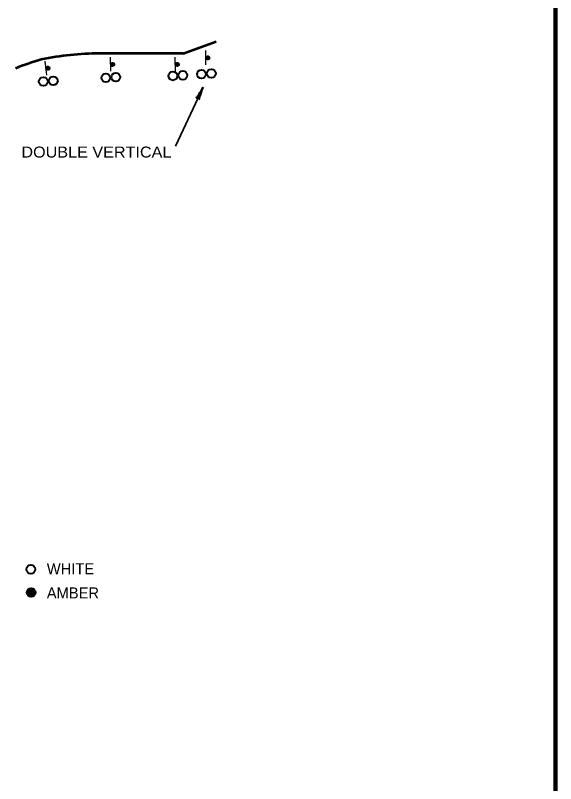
# Model space of a CAD drawing. Extents: x 393 to 1249, y -102 to 530.
# Drawn here: x 1122.7 to 1242.2, y 155.6 to 325.7 of the extents above; entities that cross this region are included whole.
import ezdxf
from ezdxf.enums import TextEntityAlignment as Align

# ---------------------------------------------------------------- set-up
doc = ezdxf.new("R2010")
doc.units = 0
doc.header["$LTSCALE"] = 0.97
doc.layers.add('1', color=7, linetype='Continuous', lineweight=40)
doc.layers.add('4', color=7, linetype='Continuous', lineweight=25)

msp = doc.modelspace()

# ---------------------------------------------------------------- linework, layer by layer
at = {"layer": '1', "lineweight": 158}
msp.add_line((1242.1684, -2.8845), (1242.1684, 523.2155), dxfattribs=at)
at = {"layer": '1', "lineweight": 13}
msp.add_line((1242.1684, -2.8845), (1242.1684, 523.2155), dxfattribs=at)
at = {"layer": '1', "lineweight": 53}
for q in [(1167.0635, 319.8655), (1141.2885, 317.206)]:
    msp.add_line((1159.7565, 317.206), q, dxfattribs=at)
at = {"layer": '1', "lineweight": 35}
msp.add_line((1158.0652, 296.7177), (1164.1645, 309.7296), dxfattribs=at)
at = {"layer": '1'}
for centre, radius in [((1165.1956, 316.2264), 0.3791), ((1165.1861, 316.2165), 0.35), ((1165.1958, 316.2167), 0.3305), ((1165.2147, 316.2462), 0.3402), ((1165.1956, 316.2264), 0.3013), ((1165.1956, 316.2264), 0.2819), ((1165.1958, 316.2167), 0.2722), ((1165.1958, 316.2167), 0.2527), ((1165.2055, 316.2169), 0.2335), ((1165.2152, 316.217), 0.2138), ((1165.2152, 316.217), 0.1944), ((1165.1961, 316.1972), 0.1555), ((1165.2347, 316.2174), 0.175), ((1165.196, 316.207), 0.1069), ((1165.2544, 316.1983), 0.1555), ((1165.264, 316.2082), 0.1461), ((1165.2739, 316.1986), 0.1166), ((1165.2836, 316.1988), 0.0977), ((1165.2933, 316.1989), 0.0778), ((1165.2321, 316.3631), 0.00972), ((1144.1669, 314.7907), 0.3791), ((1144.1573, 314.7808), 0.35), ((1144.1671, 314.781), 0.3305), ((1144.186, 314.8105), 0.3402), ((1144.1669, 314.7907), 0.3013), ((1144.1669, 314.7907), 0.2819), ((1144.1671, 314.781), 0.2722), ((1144.1671, 314.781), 0.2527), ((1144.1768, 314.7811), 0.2335), ((1144.1865, 314.7813), 0.2138), ((1144.1865, 314.7813), 0.1944), ((1144.1674, 314.7615), 0.1555), ((1144.2059, 314.7816), 0.175), ((1144.1672, 314.7712), 0.1069), ((1144.2257, 314.7625), 0.1555), ((1144.2353, 314.7724), 0.1461), ((1144.2451, 314.7629), 0.1166), ((1144.2549, 314.763), 0.0977), ((1144.2646, 314.7632), 0.0778), ((1144.2034, 314.9274), 0.00972), ((1144.284, 314.7636), 0.0583), ((1144.3035, 314.7639), 0.0389), ((1144.3229, 314.7642), 0.0194), ((1158.4394, 314.7907), 0.3791), ((1158.4299, 314.7808), 0.35), ((1158.4396, 314.781), 0.3305), ((1158.4585, 314.8105), 0.3402), ((1158.4394, 314.7907), 0.3013), ((1158.4394, 314.7907), 0.2819), ((1158.4396, 314.781), 0.2722), ((1158.4396, 314.781), 0.2527), ((1158.4493, 314.7811), 0.2335), ((1158.459, 314.7813), 0.2138), ((1158.459, 314.7813), 0.1944), ((1158.4399, 314.7615), 0.1555), ((1158.4785, 314.7816), 0.175), ((1158.4398, 314.7712), 0.1069), ((1158.4982, 314.7625), 0.1555), ((1158.5078, 314.7724), 0.1461), ((1158.5177, 314.7629), 0.1166), ((1158.5274, 314.763), 0.0977), ((1158.5371, 314.7632), 0.0778), ((1158.4759, 314.9274), 0.00972), ((1158.5565, 314.7636), 0.0583), ((1158.576, 314.7639), 0.0389), ((1158.5954, 314.7642), 0.0194), ((1165.3128, 316.1993), 0.0583), ((1165.3322, 316.1996), 0.0389), ((1165.3516, 316.2), 0.0194), ((1129.8321, 313.9483), 0.3791), ((1129.8236, 313.9375), 0.35), ((1129.8333, 313.9387), 0.3305), ((1129.849, 313.97), 0.3402), ((1129.8321, 313.9483), 0.3013), ((1129.8321, 313.9483), 0.2819), ((1129.8333, 313.9387), 0.2722), ((1129.8333, 313.9387), 0.2527), ((1129.8429, 313.9398), 0.2335), ((1129.8526, 313.941), 0.2138), ((1129.8526, 313.941), 0.1944), ((1129.8357, 313.9194), 0.1555), ((1129.8719, 313.9434), 0.175), ((1129.8345, 313.929), 0.1069), ((1129.8935, 313.9265), 0.1555), ((1129.902, 313.9373), 0.1461), ((1129.9128, 313.9288), 0.1166), ((1129.9225, 313.93), 0.0977), ((1129.8541, 314.0881), 0.00972), ((1129.9321, 313.9312), 0.0778), ((1129.9514, 313.9336), 0.0583), ((1129.9707, 313.9359), 0.0389), ((1129.99, 313.9383), 0.0194), ((1144.8664, 311.9768), 0.972), ((1157.5134, 312.2419), 0.972), ((1159.7079, 312.3834), 0.972), ((1163.816, 312.6485), 0.972), ((1166.0105, 312.7901), 0.972), ((1128.847, 311.022), 0.972), ((1131.0415, 311.1636), 0.972), ((1142.6719, 311.8352), 0.972), ((1126.0652, 203.0406), 0.972), ((1126.1406, 197.9056), 0.972), ((1126.1274, 197.9483), 0.8529), ((1125.7081, 197.6815), 0.3923), ((1126.1147, 197.923), 0.7878), ((1126.1275, 197.8848), 0.7017), ((1126.0512, 197.6307), 0.6228), ((1126.1147, 197.9611), 0.5846), ((1126.2672, 197.7705), 0.6414), ((1126.0893, 197.8848), 0.4322), ((1126.191, 197.8086), 0.5216), ((1126.1401, 198.139), 0.3831), ((1126.1147, 197.9484), 0.3558), ((1126.3689, 197.6688), 0.5762), ((1126.1402, 197.9484), 0.2049), ((1126.1401, 197.923), 0.0508)]:
    msp.add_circle(centre, radius, dxfattribs=at)
at = {"layer": '1', "lineweight": 53}
for centre, radius, start, end in [((1141.4931, 251.7446), 65.4618, 90.17904, 101.54441), ((1150.8351, 241.2494), 77.9341, 106.73651, 111.19585)]:
    msp.add_arc(centre, radius, start, end, dxfattribs=at)
at = {"layer": '1'}
for centre, major_axis, ratio, start_param, end_param in [((1163.5161, 308.8307), (-0.8792, -1.4734), 0.07063, 6.28230741, 8.55970261), ((1163.9576, 308.6552), (0.5993, 1.636), 0.122415, 0.89635335, 3.14159265)]:
    msp.add_ellipse(centre, major_axis=major_axis, ratio=ratio, start_param=start_param, end_param=end_param, dxfattribs=at)
at = {"layer": '4'}
for p, q in [((1143.7847, 313.2968), (1143.7302, 316.4067)), ((1158.0571, 313.2968), (1158.0028, 316.4067)), ((1164.8134, 314.7325), (1164.759, 317.8424)), ((1129.6081, 312.4226), (1129.2289, 315.5097))]:
    msp.add_line(p, q, dxfattribs=at)
for centre in [(1165.1955, 316.2361), (1144.1667, 314.8004), (1158.4392, 314.8004), (1129.8309, 313.9579)]:
    msp.add_circle(centre, 0.3985, dxfattribs=at)

# ---------------------------------------------------------------- texts
at = {"layer": '1', "width": 1.1}
msp.add_text('DOUBLE VERTICAL', height=2.43, dxfattribs=at).set_placement((1140.5807, 294.1811), align=Align.CENTER)
at = {"layer": '1'}
for s, p in [('WHITE', (1129.6108, 201.9518)), ('AMBER', (1129.6108, 196.6058))]:
    msp.add_text(s, height=2.43, dxfattribs=at).set_placement(p)

doc.saveas('drawing.dxf')
